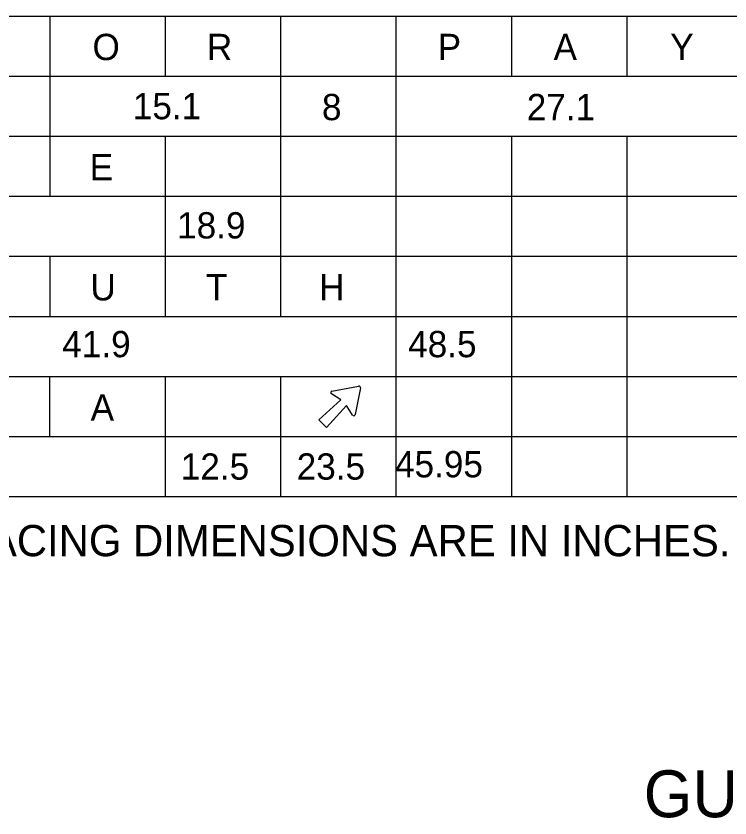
# Model space of a CAD drawing. Extents: x 10268312 to 10268472, y 2142583 to 2142688.
# Drawn here: x 10268414.76 to 10268433.77, y 2142587.67 to 2142609.03 of the extents above; entities that cross this region are included whole.
import ezdxf

# ---------------------------------------------------------------- set-up
doc = ezdxf.new("R2010")
doc.units = 0
for name, color, linetype in [('GSBWFill', 7, 'Continuous'), ('SignPanel', 7, 'Continuous'), ('SumBoxLines_dp', 7, 'Continuous'), ('SumBoxLinesMin_dp', 7, 'Continuous'), ('TextLabel', 7, 'Continuous'), ('TextMisc', 7, 'Continuous'), ('TextNotes', 7, 'Continuous')]:
    doc.layers.add(name, color=color, linetype=linetype)

msp = doc.modelspace()

# ---------------------------------------------------------------- linework, layer by layer
at = {"layer": 'SignPanel'}
for points in [[(10268423.172, 2142599.038), (10268423.883, 2142599.176)], [(10268423.93, 2142599.129), (10268423.792, 2142598.418)], [(10268423.718, 2142598.405), (10268423.564, 2142598.657), (10268423.028, 2142598.072), (10268422.826, 2142598.274), (10268423.411, 2142598.81), (10268423.158, 2142598.965)]]:
    msp.add_lwpolyline(points, dxfattribs=at)
for centre, start, end in [((10268423.179, 2142598.999), 100.9777, 238.5155), ((10268423.891, 2142599.137), 349.0223, 100.9777), ((10268423.753, 2142598.426), 211.4845, 349.0223)]:
    msp.add_arc(centre, 0.0401, start, end, dxfattribs=at)
at = {"layer": 'SumBoxLines_dp'}
for p, q in [((10268395.48, 2142609.032), (10268470.98, 2142609.032)), ((10268395.48, 2142609.032), (10268470.98, 2142609.032)), ((10268415.657, 2142609.032), (10268415.657, 2142607.432)), ((10268415.657, 2142609.032), (10268415.657, 2142607.432)), ((10268415.657, 2142609.032), (10268415.657, 2142604.232)), ((10268418.73, 2142609.032), (10268418.73, 2142607.432)), ((10268418.73, 2142609.032), (10268418.73, 2142607.432)), ((10268421.804, 2142609.032), (10268421.804, 2142605.832)), ((10268421.804, 2142609.032), (10268421.804, 2142607.432)), ((10268421.804, 2142609.032), (10268421.804, 2142601.032)), ((10268424.877, 2142609.032), (10268424.877, 2142607.432)), ((10268424.877, 2142609.032), (10268424.877, 2142607.432)), ((10268424.877, 2142609.032), (10268424.877, 2142596.232)), ((10268427.951, 2142609.032), (10268427.951, 2142607.432)), ((10268427.951, 2142609.032), (10268427.951, 2142607.432)), ((10268431.024, 2142609.032), (10268431.024, 2142607.432)), ((10268431.024, 2142609.032), (10268431.024, 2142607.432)), ((10268395.48, 2142605.832), (10268470.98, 2142605.832)), ((10268415.657, 2142605.832), (10268415.657, 2142604.232)), ((10268418.73, 2142605.832), (10268418.73, 2142604.232)), ((10268418.73, 2142605.832), (10268418.73, 2142601.032)), ((10268421.804, 2142605.832), (10268421.804, 2142604.232)), ((10268424.877, 2142605.832), (10268424.877, 2142604.232)), ((10268427.951, 2142605.832), (10268427.951, 2142596.232)), ((10268431.024, 2142605.832), (10268431.024, 2142596.232)), ((10268395.48, 2142602.632), (10268470.98, 2142602.632)), ((10268415.657, 2142602.632), (10268415.657, 2142601.032)), ((10268415.657, 2142602.632), (10268415.657, 2142601.032)), ((10268418.73, 2142602.632), (10268418.73, 2142601.032)), ((10268424.877, 2142602.632), (10268424.877, 2142597.832)), ((10268395.48, 2142599.432), (10268470.98, 2142599.432)), ((10268415.657, 2142597.832), (10268415.657, 2142599.432)), ((10268418.73, 2142599.432), (10268418.73, 2142596.232)), ((10268421.804, 2142599.432), (10268421.804, 2142596.232)), ((10268395.48, 2142596.232), (10268470.98, 2142596.232))]:
    msp.add_line(p, q, dxfattribs=at)
at = {"layer": 'SumBoxLinesMin_dp'}
for p, q in [((10268395.48, 2142607.432), (10268470.98, 2142607.432)), ((10268395.48, 2142604.232), (10268470.98, 2142604.232)), ((10268395.48, 2142601.032), (10268470.98, 2142601.032)), ((10268395.48, 2142597.832), (10268470.98, 2142597.832))]:
    msp.add_line(p, q, dxfattribs=at)

# ---------------------------------------------------------------- texts
at = {"layer": 'GSBWFill'}
msp.add_text('15.1', height=0.7, dxfattribs=at).set_placement((10268417.868, 2142606.283))
at = {"layer": 'TextLabel'}
for s, p in [('O', (10268416.794, 2142607.858)), ('R', (10268419.842, 2142607.858)), ('P', (10268425.989, 2142607.858)), ('A', (10268429.076, 2142607.858)), ('Y', (10268432.184, 2142607.858)), ('8', (10268422.906, 2142606.258)), ('27.1', (10268428.362, 2142606.258)), ('E', (10268416.719, 2142604.657)), ('18.9', (10268419.048, 2142603.107)), ('U', (10268416.74, 2142601.457)), ('T', (10268419.816, 2142601.457)), ('H', (10268422.831, 2142601.457)), ('41.9', (10268415.989, 2142599.944)), ('48.5', (10268425.202, 2142599.944)), ('A', (10268416.745, 2142598.257)), ('12.5', (10268419.146, 2142596.683)), ('23.5', (10268422.234, 2142596.683)), ('45.95', (10268424.852, 2142596.744))]:
    msp.add_text(s, height=0.7, dxfattribs=at).set_placement(p)
at = {"layer": 'TextMisc'}
msp.add_text('     GUIDE SIGN WORKSHEET      ', height=1.25, rotation=360, dxfattribs=at).set_placement((10268429.155, 2142587.69))
at = {"layer": 'TextNotes'}
msp.add_text('NOTE:  WIDTH - HORIZONTAL SPACING DIMENSIONS ARE IN INCHES.', height=0.83333, dxfattribs=at).set_placement((10268396.392, 2142594.643))

doc.saveas('drawing.dxf')
